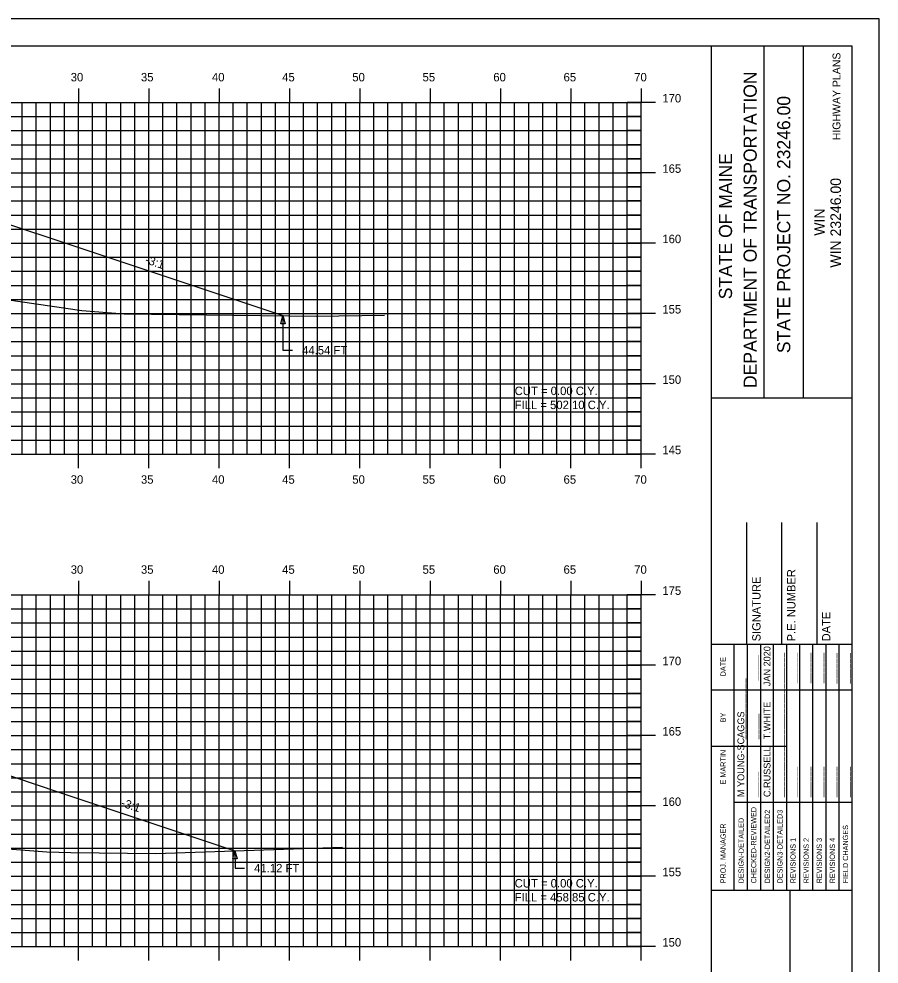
# Model space of a CAD drawing. Extents: x 1140981 to 1141151, y 608981 to 609091.
# Drawn here: x 1141089.5 to 1141150.7, y 609024.1 to 609091.3 of the extents above; entities that cross this region are included whole.
import ezdxf

# ---------------------------------------------------------------- set-up
doc = ezdxf.new("R2010")
doc.units = 0
for name, color, linetype in [('ANNOTATION', 7, 'Continuous'), ('BORDER', 7, 'Continuous'), ('D_Roadway_SlopeLines', 7, 'Continuous'), ('D_Text_Standard', 7, 'Continuous'), ('H_V ANNOTATION', 7, 'Continuous'), ('HIGHWAY_TITLE', 7, 'Continuous'), ('MAJOR', 7, 'Continuous'), ('MINOR', 7, 'Continuous'), ('PLOT BOUNDARY', 7, 'Continuous'), ('S_Roadway_Centerline', 7, 'Continuous')]:
    doc.layers.add(name, color=color, linetype=linetype)

msp = doc.modelspace()

# ---------------------------------------------------------------- linework, layer by layer
for points in [[(1141018.694, 609070.301), (1141034.295, 609075.501), (1141037.295, 609076.501), (1141044.764, 609078.991), (1141044.765, 609078.991), (1141052.758, 609079.311), (1141063.758, 609079.531), (1141074.758, 609079.311), (1141081.758, 609079.031), (1141089.29, 609076.52), (1141092.29, 609075.52), (1141108.295, 609070.185)], [(1141015.324, 609031.014), (1141031.055, 609036.258), (1141034.055, 609037.258), (1141041.302, 609039.673), (1141041.303, 609039.673), (1141052.758, 609040.132), (1141063.758, 609040.352), (1141074.758, 609040.132), (1141081.758, 609039.852), (1141089.29, 609037.341), (1141092.29, 609036.341), (1141104.882, 609032.144)]]:
    msp.add_lwpolyline(points)
at = {"layer": 'BORDER'}
for p, q in [((1141138.758, 608984.335), (1141138.758, 609089.335)), ((1141142.486, 609064.332), (1141142.486, 609089.332)), ((1141145.281, 609064.332), (1141145.281, 609089.332)), ((1141138.759, 609064.329), (1141148.758, 609064.329)), ((1141141.258, 609046.838), (1141141.258, 609055.485)), ((1141143.758, 609046.838), (1141143.758, 609055.485)), ((1141146.258, 609046.838), (1141146.258, 609055.485)), ((1141138.758, 609046.838), (1141148.758, 609046.838)), ((1141138.758, 609029.338), (1141148.758, 609029.338)), ((1141144.349, 608994.338), (1141144.349, 609029.338))]:
    msp.add_line(p, q, dxfattribs=at)
msp.add_lwpolyline([(1140988.758, 608984.335), (1141148.758, 608984.335), (1141148.758, 609089.335), (1140988.758, 609089.335)], close=True, dxfattribs=at)
for points in [[(1141140.373, 609043.588), (1141140.373, 609046.838)], [(1141141.305, 609029.341), (1141141.305, 609046.838)], [(1141142.237, 609046.838), (1141142.237, 609029.341)], [(1141143.169, 609029.341), (1141143.169, 609046.838)], [(1141144.1, 609029.341), (1141144.1, 609046.838)], [(1141145.032, 609029.341), (1141145.032, 609046.838)], [(1141145.964, 609029.341), (1141145.964, 609046.838)], [(1141146.895, 609029.341), (1141146.895, 609046.838)], [(1141147.827, 609029.341), (1141147.827, 609046.838)], [(1141140.374, 609029.341), (1141140.374, 609046.132)], [(1141138.758, 609043.588), (1141148.758, 609043.588)], [(1141138.758, 609039.588), (1141140.374, 609039.588)], [(1141140.373, 609039.588), (1141144.099, 609039.588)], [(1141140.373, 609035.588), (1141148.758, 609035.588)]]:
    msp.add_lwpolyline(points, dxfattribs=at)
at = {"layer": 'D_Roadway_SlopeLines'}
for points in [[(1141089.29, 609076.52), (1141092.29, 609075.52)], [(1141092.29, 609075.52), (1141108.295, 609070.185)], [(1141089.29, 609037.341), (1141092.29, 609036.341)], [(1141092.29, 609036.341), (1141104.882, 609032.144)]]:
    msp.add_lwpolyline(points, dxfattribs=at)
at = {"layer": 'D_Text_Standard'}
for points in [[(1141108.295, 609070.185), (1141108.44, 609069.603), (1141108.149, 609069.603)], [(1141104.882, 609032.144), (1141105.028, 609031.562), (1141104.737, 609031.561)]]:
    msp.add_lwpolyline(points, close=True, dxfattribs=at)
for points in [[(1141108.295, 609070.185), (1141108.292, 609067.726), (1141108.972, 609067.726)], [(1141104.882, 609032.144), (1141104.884, 609030.908), (1141105.564, 609030.908)]]:
    msp.add_lwpolyline(points, dxfattribs=at)
at = {"layer": 'MAJOR'}
for p, q in [((1141093.758, 609086.337), (1141093.758, 609085.335)), ((1141098.758, 609086.337), (1141098.758, 609085.335)), ((1141103.758, 609086.337), (1141103.758, 609085.335)), ((1141108.758, 609086.337), (1141108.758, 609085.335)), ((1141113.758, 609086.337), (1141113.758, 609085.335)), ((1141118.758, 609086.337), (1141118.758, 609085.335)), ((1141123.758, 609086.337), (1141123.758, 609085.335)), ((1141128.758, 609086.337), (1141128.758, 609085.335)), ((1141133.758, 609086.337), (1141133.758, 609085.335)), ((1140993.758, 609085.335), (1141133.758, 609085.335)), ((1140993.758, 609085.335), (1141133.758, 609085.335)), ((1141093.758, 609060.335), (1141093.758, 609085.335)), ((1141098.758, 609060.335), (1141098.758, 609085.335)), ((1141103.758, 609060.335), (1141103.758, 609085.335)), ((1141108.758, 609060.335), (1141108.758, 609085.335)), ((1141113.758, 609060.335), (1141113.758, 609085.335)), ((1141118.758, 609060.335), (1141118.758, 609085.335)), ((1141123.758, 609060.335), (1141123.758, 609085.335)), ((1141128.758, 609060.335), (1141128.758, 609085.335)), ((1141134.76, 609085.335), (1141132.756, 609085.335)), ((1141133.758, 609060.335), (1141133.758, 609085.335)), ((1141133.758, 609060.335), (1141133.758, 609085.335)), ((1140993.758, 609080.335), (1141133.758, 609080.335)), ((1141134.76, 609080.335), (1141132.756, 609080.335)), ((1140993.758, 609075.335), (1141133.758, 609075.335)), ((1141134.76, 609075.335), (1141132.756, 609075.335)), ((1140993.758, 609070.335), (1141133.758, 609070.335)), ((1141134.76, 609070.335), (1141132.756, 609070.335)), ((1140993.758, 609065.335), (1141133.758, 609065.335)), ((1141134.76, 609065.335), (1141132.756, 609065.335)), ((1140993.758, 609060.335), (1141133.758, 609060.335)), ((1140993.758, 609060.335), (1141133.758, 609060.335)), ((1141093.758, 609059.333), (1141093.758, 609060.335)), ((1141098.758, 609059.333), (1141098.758, 609060.335)), ((1141103.758, 609059.333), (1141103.758, 609060.335)), ((1141108.758, 609059.333), (1141108.758, 609060.335)), ((1141113.758, 609059.333), (1141113.758, 609060.335)), ((1141118.758, 609059.333), (1141118.758, 609060.335)), ((1141123.758, 609059.333), (1141123.758, 609060.335)), ((1141128.758, 609059.333), (1141128.758, 609060.335)), ((1141134.76, 609060.335), (1141132.756, 609060.335)), ((1141133.758, 609059.333), (1141133.758, 609060.335)), ((1141093.758, 609051.337), (1141093.758, 609050.335)), ((1141098.758, 609051.337), (1141098.758, 609050.335)), ((1141103.758, 609051.337), (1141103.758, 609050.335)), ((1141108.758, 609051.337), (1141108.758, 609050.335)), ((1141113.758, 609051.337), (1141113.758, 609050.335)), ((1141118.758, 609051.337), (1141118.758, 609050.335)), ((1141123.758, 609051.337), (1141123.758, 609050.335)), ((1141128.758, 609051.337), (1141128.758, 609050.335)), ((1141133.758, 609051.337), (1141133.758, 609050.335)), ((1140993.758, 609050.335), (1141133.758, 609050.335)), ((1140993.758, 609050.335), (1141133.758, 609050.335)), ((1141093.758, 609025.335), (1141093.758, 609050.335)), ((1141098.758, 609025.335), (1141098.758, 609050.335)), ((1141103.758, 609025.335), (1141103.758, 609050.335)), ((1141108.758, 609025.335), (1141108.758, 609050.335)), ((1141113.758, 609025.335), (1141113.758, 609050.335)), ((1141118.758, 609025.335), (1141118.758, 609050.335)), ((1141123.758, 609025.335), (1141123.758, 609050.335)), ((1141128.758, 609025.335), (1141128.758, 609050.335)), ((1141134.76, 609050.335), (1141132.756, 609050.335)), ((1141133.758, 609025.335), (1141133.758, 609050.335)), ((1141133.758, 609025.335), (1141133.758, 609050.335)), ((1140993.758, 609045.335), (1141133.758, 609045.335)), ((1141134.76, 609045.335), (1141132.756, 609045.335)), ((1140993.758, 609040.335), (1141133.758, 609040.335)), ((1141134.76, 609040.335), (1141132.756, 609040.335)), ((1140993.758, 609035.335), (1141133.758, 609035.335)), ((1141134.76, 609035.335), (1141132.756, 609035.335)), ((1140993.758, 609030.335), (1141133.758, 609030.335)), ((1141134.76, 609030.335), (1141132.756, 609030.335)), ((1140993.758, 609025.335), (1141133.758, 609025.335)), ((1140993.758, 609025.335), (1141133.758, 609025.335)), ((1141093.758, 609024.333), (1141093.758, 609025.335)), ((1141098.758, 609024.333), (1141098.758, 609025.335)), ((1141103.758, 609024.333), (1141103.758, 609025.335)), ((1141108.758, 609024.333), (1141108.758, 609025.335)), ((1141113.758, 609024.333), (1141113.758, 609025.335)), ((1141118.758, 609024.333), (1141118.758, 609025.335)), ((1141123.758, 609024.333), (1141123.758, 609025.335)), ((1141128.758, 609024.333), (1141128.758, 609025.335)), ((1141134.76, 609025.335), (1141132.756, 609025.335)), ((1141133.758, 609024.333), (1141133.758, 609025.335))]:
    msp.add_line(p, q, dxfattribs=at)
at = {"layer": 'MINOR'}
for p, q in [((1141089.758, 609060.335), (1141089.758, 609085.335)), ((1141090.758, 609060.335), (1141090.758, 609085.335)), ((1141091.758, 609060.335), (1141091.758, 609085.335)), ((1141092.758, 609060.335), (1141092.758, 609085.335)), ((1141094.758, 609060.335), (1141094.758, 609085.335)), ((1141095.758, 609060.335), (1141095.758, 609085.335)), ((1141096.758, 609060.335), (1141096.758, 609085.335)), ((1141097.758, 609060.335), (1141097.758, 609085.335)), ((1141099.758, 609060.335), (1141099.758, 609085.335)), ((1141100.758, 609060.335), (1141100.758, 609085.335)), ((1141101.758, 609060.335), (1141101.758, 609085.335)), ((1141102.758, 609060.335), (1141102.758, 609085.335)), ((1141104.758, 609060.335), (1141104.758, 609085.335)), ((1141105.758, 609060.335), (1141105.758, 609085.335)), ((1141106.758, 609060.335), (1141106.758, 609085.335)), ((1141107.758, 609060.335), (1141107.758, 609085.335)), ((1141109.758, 609060.335), (1141109.758, 609085.335)), ((1141110.758, 609060.335), (1141110.758, 609085.335)), ((1141111.758, 609060.335), (1141111.758, 609085.335)), ((1141112.758, 609060.335), (1141112.758, 609085.335)), ((1141114.758, 609060.335), (1141114.758, 609085.335)), ((1141115.758, 609060.335), (1141115.758, 609085.335)), ((1141116.758, 609060.335), (1141116.758, 609085.335)), ((1141117.758, 609060.335), (1141117.758, 609085.335)), ((1141119.758, 609060.335), (1141119.758, 609085.335)), ((1141120.758, 609060.335), (1141120.758, 609085.335)), ((1141121.758, 609060.335), (1141121.758, 609085.335)), ((1141122.758, 609060.335), (1141122.758, 609085.335)), ((1141124.758, 609060.335), (1141124.758, 609085.335)), ((1141125.758, 609060.335), (1141125.758, 609085.335)), ((1141126.758, 609060.335), (1141126.758, 609085.335)), ((1141127.758, 609060.335), (1141127.758, 609085.335)), ((1141129.758, 609060.335), (1141129.758, 609085.335)), ((1141130.758, 609060.335), (1141130.758, 609085.335)), ((1141131.758, 609060.335), (1141131.758, 609085.335)), ((1141132.758, 609060.335), (1141132.758, 609085.335)), ((1140993.758, 609084.335), (1141133.758, 609084.335)), ((1141133.758, 609084.335), (1141132.756, 609084.335)), ((1140993.758, 609083.335), (1141133.758, 609083.335)), ((1141133.758, 609083.335), (1141132.756, 609083.335)), ((1140993.758, 609082.335), (1141133.758, 609082.335)), ((1141133.758, 609082.335), (1141132.756, 609082.335)), ((1140993.758, 609081.335), (1141133.758, 609081.335)), ((1141133.758, 609081.335), (1141132.756, 609081.335)), ((1140993.758, 609079.335), (1141133.758, 609079.335)), ((1141133.758, 609079.335), (1141132.756, 609079.335)), ((1140993.758, 609078.335), (1141133.758, 609078.335)), ((1141133.758, 609078.335), (1141132.756, 609078.335)), ((1140993.758, 609077.335), (1141133.758, 609077.335)), ((1141133.758, 609077.335), (1141132.756, 609077.335)), ((1140993.758, 609076.335), (1141133.758, 609076.335)), ((1141133.758, 609076.335), (1141132.756, 609076.335)), ((1140993.758, 609074.335), (1141133.758, 609074.335)), ((1141133.758, 609074.335), (1141132.756, 609074.335)), ((1140993.758, 609073.335), (1141133.758, 609073.335)), ((1141133.758, 609073.335), (1141132.756, 609073.335)), ((1140993.758, 609072.335), (1141133.758, 609072.335)), ((1141133.758, 609072.335), (1141132.756, 609072.335)), ((1140993.758, 609071.335), (1141133.758, 609071.335)), ((1141133.758, 609071.335), (1141132.756, 609071.335)), ((1140993.758, 609069.335), (1141133.758, 609069.335)), ((1141133.758, 609069.335), (1141132.756, 609069.335)), ((1140993.758, 609068.335), (1141133.758, 609068.335)), ((1141133.758, 609068.335), (1141132.756, 609068.335)), ((1140993.758, 609067.335), (1141133.758, 609067.335)), ((1141133.758, 609067.335), (1141132.756, 609067.335)), ((1140993.758, 609066.335), (1141133.758, 609066.335)), ((1141133.758, 609066.335), (1141132.756, 609066.335)), ((1140993.758, 609064.335), (1141133.758, 609064.335)), ((1141133.758, 609064.335), (1141132.756, 609064.335)), ((1140993.758, 609063.335), (1141133.758, 609063.335)), ((1141133.758, 609063.335), (1141132.756, 609063.335)), ((1140993.758, 609062.335), (1141133.758, 609062.335)), ((1141133.758, 609062.335), (1141132.756, 609062.335)), ((1140993.758, 609061.335), (1141133.758, 609061.335)), ((1141133.758, 609061.335), (1141132.756, 609061.335)), ((1141089.758, 609025.335), (1141089.758, 609050.335)), ((1141090.758, 609025.335), (1141090.758, 609050.335)), ((1141091.758, 609025.335), (1141091.758, 609050.335)), ((1141092.758, 609025.335), (1141092.758, 609050.335)), ((1141094.758, 609025.335), (1141094.758, 609050.335)), ((1141095.758, 609025.335), (1141095.758, 609050.335)), ((1141096.758, 609025.335), (1141096.758, 609050.335)), ((1141097.758, 609025.335), (1141097.758, 609050.335)), ((1141099.758, 609025.335), (1141099.758, 609050.335)), ((1141100.758, 609025.335), (1141100.758, 609050.335)), ((1141101.758, 609025.335), (1141101.758, 609050.335)), ((1141102.758, 609025.335), (1141102.758, 609050.335)), ((1141104.758, 609025.335), (1141104.758, 609050.335)), ((1141105.758, 609025.335), (1141105.758, 609050.335)), ((1141106.758, 609025.335), (1141106.758, 609050.335)), ((1141107.758, 609025.335), (1141107.758, 609050.335)), ((1141109.758, 609025.335), (1141109.758, 609050.335)), ((1141110.758, 609025.335), (1141110.758, 609050.335)), ((1141111.758, 609025.335), (1141111.758, 609050.335)), ((1141112.758, 609025.335), (1141112.758, 609050.335)), ((1141114.758, 609025.335), (1141114.758, 609050.335)), ((1141115.758, 609025.335), (1141115.758, 609050.335)), ((1141116.758, 609025.335), (1141116.758, 609050.335)), ((1141117.758, 609025.335), (1141117.758, 609050.335)), ((1141119.758, 609025.335), (1141119.758, 609050.335)), ((1141120.758, 609025.335), (1141120.758, 609050.335)), ((1141121.758, 609025.335), (1141121.758, 609050.335)), ((1141122.758, 609025.335), (1141122.758, 609050.335)), ((1141124.758, 609025.335), (1141124.758, 609050.335)), ((1141125.758, 609025.335), (1141125.758, 609050.335)), ((1141126.758, 609025.335), (1141126.758, 609050.335)), ((1141127.758, 609025.335), (1141127.758, 609050.335)), ((1141129.758, 609025.335), (1141129.758, 609050.335)), ((1141130.758, 609025.335), (1141130.758, 609050.335)), ((1141131.758, 609025.335), (1141131.758, 609050.335)), ((1141132.758, 609025.335), (1141132.758, 609050.335)), ((1140993.758, 609049.335), (1141133.758, 609049.335)), ((1141133.758, 609049.335), (1141132.756, 609049.335)), ((1140993.758, 609048.335), (1141133.758, 609048.335)), ((1141133.758, 609048.335), (1141132.756, 609048.335)), ((1140993.758, 609047.335), (1141133.758, 609047.335)), ((1141133.758, 609047.335), (1141132.756, 609047.335)), ((1140993.758, 609046.335), (1141133.758, 609046.335)), ((1141133.758, 609046.335), (1141132.756, 609046.335)), ((1140993.758, 609044.335), (1141133.758, 609044.335)), ((1141133.758, 609044.335), (1141132.756, 609044.335)), ((1140993.758, 609043.335), (1141133.758, 609043.335)), ((1141133.758, 609043.335), (1141132.756, 609043.335)), ((1140993.758, 609042.335), (1141133.758, 609042.335)), ((1141133.758, 609042.335), (1141132.756, 609042.335)), ((1140993.758, 609041.335), (1141133.758, 609041.335)), ((1141133.758, 609041.335), (1141132.756, 609041.335)), ((1140993.758, 609039.335), (1141133.758, 609039.335)), ((1141133.758, 609039.335), (1141132.756, 609039.335)), ((1140993.758, 609038.335), (1141133.758, 609038.335)), ((1141133.758, 609038.335), (1141132.756, 609038.335)), ((1140993.758, 609037.335), (1141133.758, 609037.335)), ((1141133.758, 609037.335), (1141132.756, 609037.335)), ((1140993.758, 609036.335), (1141133.758, 609036.335)), ((1141133.758, 609036.335), (1141132.756, 609036.335)), ((1140993.758, 609034.335), (1141133.758, 609034.335)), ((1141133.758, 609034.335), (1141132.756, 609034.335)), ((1140993.758, 609033.335), (1141133.758, 609033.335)), ((1141133.758, 609033.335), (1141132.756, 609033.335)), ((1140993.758, 609032.335), (1141133.758, 609032.335)), ((1141133.758, 609032.335), (1141132.756, 609032.335)), ((1140993.758, 609031.335), (1141133.758, 609031.335)), ((1141133.758, 609031.335), (1141132.756, 609031.335)), ((1140993.758, 609029.335), (1141133.758, 609029.335)), ((1141133.758, 609029.335), (1141132.756, 609029.335)), ((1140993.758, 609028.335), (1141133.758, 609028.335)), ((1141133.758, 609028.335), (1141132.756, 609028.335)), ((1140993.758, 609027.335), (1141133.758, 609027.335)), ((1141133.758, 609027.335), (1141132.756, 609027.335)), ((1140993.758, 609026.335), (1141133.758, 609026.335)), ((1141133.758, 609026.335), (1141132.756, 609026.335))]:
    msp.add_line(p, q, dxfattribs=at)
at = {"layer": 'PLOT BOUNDARY'}
msp.add_lwpolyline([(1140980.664, 608981.276), (1141150.664, 608981.276), (1141150.664, 609091.276), (1140980.664, 609091.276)], close=True, dxfattribs=at)
at = {"layer": 'S_Roadway_Centerline'}
for points in [[(1140993.758, 609070.235), (1141016.927, 609070.323), (1141025.835, 609070.211), (1141031.23, 609070.816), (1141045.025, 609071.913), (1141046.887, 609072.758), (1141050.236, 609074.313), (1141052.144, 609074.689), (1141053.6, 609074.965), (1141057.959, 609075.178), (1141064.255, 609075.378), (1141069.594, 609075.216), (1141075.604, 609075.039), (1141077.446, 609074.821), (1141079.228, 609074.497), (1141085.647, 609072.383), (1141088.632, 609071.329), (1141093.986, 609070.537), (1141096.999, 609070.318), (1141110.65, 609070.157), (1141115.506, 609070.212)], [(1140993.758, 609030.733), (1141009.977, 609030.874), (1141026.763, 609031.313), (1141030.432, 609031.56), (1141045.208, 609032.752), (1141047.834, 609033.947), (1141049.661, 609034.555), (1141051.778, 609034.94), (1141052.932, 609035.025), (1141057.344, 609035.19), (1141063.779, 609035.507), (1141070.513, 609035.304), (1141074.764, 609035.173), (1141076.322, 609035.016), (1141078.692, 609034.736), (1141083.759, 609032.911), (1141084.999, 609032.561), (1141091.498, 609032.059), (1141093.213, 609032.024), (1141099.245, 609031.951), (1141112.53, 609032.405)]]:
    msp.add_lwpolyline(points, dxfattribs=at)

# ---------------------------------------------------------------- texts
at = {"layer": 'ANNOTATION'}
for p in [(1141098.442, 609073.923), (1141096.735, 609035.313)]:
    msp.add_text('-3:1', height=0.6, rotation=341.56505, dxfattribs=at).set_placement(p)
at = {"layer": 'BORDER'}
for s, height, p in [('DEPARTMENT OF TRANSPORTATION', 0.93176, (1141141.965, 609065.041)), ('STATE PROJECT NO. 23246.00', 0.93176, (1141144.35, 609067.517)), ('STATE OF MAINE', 0.93176, (1141140.213, 609071.347)), ('WIN 23246.00', 0.74527, (1141147.953, 609073.596)), ('WIN', 0.7453, (1141146.795, 609075.865)), ('P.E. NUMBER', 0.59055, (1141144.719, 609047.03)), ('SIGNATURE', 0.5906, (1141142.238, 609047.03)), ('DATE', 0.5906, (1141147.199, 609047.03)), ('JAN 2020', 0.4845, (1141142.944, 609043.843)), ('DATE', 0.3714, (1141139.762, 609044.544)), ('_____', 0.4845, (1141141.975, 609044.243)), ('______', 0.4845, (1141143.839, 609044.063)), ('______', 0.4845, (1141144.77, 609044.065)), ('______', 0.4845, (1141145.702, 609044.067)), ('______', 0.4845, (1141146.634, 609044.067)), ('______', 0.4845, (1141147.565, 609044.036)), ('______', 0.4845, (1141148.497, 609044.036)), ('____________', 0.48455, (1141141.081, 609040.073)), ('____________', 0.48455, (1141143.839, 609040.073)), ('T.WHITE', 0.4845, (1141142.944, 609040.073)), ('BY', 0.3714, (1141139.762, 609041.273)), ('M YOUNG-SCAGGS', 0.48455, (1141141.081, 609035.961)), ('_____', 0.4845, (1141142.012, 609040.073)), ('____________', 0.48455, (1141143.839, 609035.961)), ('E MARTIN', 0.3727, (1141139.762, 609036.855)), ('C.RUSSELL', 0.4845, (1141142.944, 609035.961)), ('_____', 0.4845, (1141141.975, 609035.961)), ('______', 0.4845, (1141144.77, 609035.961)), ('______', 0.4845, (1141145.702, 609035.961)), ('______', 0.4845, (1141146.634, 609035.961)), ('______', 0.4845, (1141147.565, 609035.961)), ('______', 0.4845, (1141148.497, 609035.961)), ('CHECKED-REVIEWED', 0.37275, (1141141.939, 609029.826)), ('DESIGN2-DETAILED2', 0.37275, (1141142.908, 609029.826)), ('DESIGN3-DETAILED3', 0.37275, (1141143.802, 609029.826)), ('DESIGN-DETAILED', 0.37275, (1141141.044, 609029.826)), ('PROJ. MANAGER', 0.37275, (1141139.762, 609029.826)), ('FIELD CHANGES', 0.37275, (1141148.461, 609029.826)), ('REVISIONS 1', 0.37275, (1141144.734, 609029.826)), ('REVISIONS 2', 0.37275, (1141145.666, 609029.826)), ('REVISIONS 3', 0.37275, (1141146.597, 609029.826)), ('REVISIONS 4', 0.37275, (1141147.529, 609029.826))]:
    msp.add_text(s, height=height, rotation=90, dxfattribs=at).set_placement(p)
at = {"layer": 'D_Text_Standard'}
for s, p in [('44.54 FT', (1141109.652, 609067.426)), ('CUT = 0.00 C.Y.', (1141124.758, 609064.535)), ('FILL = 502.10 C.Y.', (1141124.758, 609063.539)), ('41.12 FT', (1141106.244, 609030.608)), ('CUT = 0.00 C.Y.', (1141124.758, 609029.535)), ('FILL = 458.85 C.Y.', (1141124.758, 609028.539))]:
    msp.add_text(s, height=0.6, dxfattribs=at).set_placement(p)
at = {"layer": 'H_V ANNOTATION'}
for s, p in [('30', (1141093.206, 609086.835)), ('35', (1141098.198, 609086.835)), ('40', (1141103.244, 609086.835)), ('45', (1141108.236, 609086.835)), ('50', (1141113.222, 609086.835)), ('55', (1141118.214, 609086.835)), ('60', (1141123.244, 609086.835)), ('65', (1141128.236, 609086.835)), ('70', (1141133.26, 609086.835)), ('170', (1141135.258, 609085.335)), ('165', (1141135.258, 609080.335)), ('160', (1141135.258, 609075.335)), ('155', (1141135.258, 609070.335)), ('150', (1141135.258, 609065.335)), ('145', (1141135.258, 609060.335)), ('30', (1141093.206, 609058.235)), ('35', (1141098.198, 609058.235)), ('40', (1141103.244, 609058.235)), ('45', (1141108.236, 609058.235)), ('50', (1141113.222, 609058.235)), ('55', (1141118.214, 609058.235)), ('60', (1141123.244, 609058.235)), ('65', (1141128.236, 609058.235)), ('70', (1141133.26, 609058.235)), ('30', (1141093.206, 609051.835)), ('35', (1141098.198, 609051.835)), ('40', (1141103.244, 609051.835)), ('45', (1141108.236, 609051.835)), ('50', (1141113.222, 609051.835)), ('55', (1141118.214, 609051.835)), ('60', (1141123.244, 609051.835)), ('65', (1141128.236, 609051.835)), ('70', (1141133.26, 609051.835)), ('175', (1141135.258, 609050.335)), ('170', (1141135.258, 609045.335)), ('165', (1141135.258, 609040.335)), ('160', (1141135.258, 609035.335)), ('155', (1141135.258, 609030.335)), ('150', (1141135.258, 609025.335))]:
    msp.add_text(s, height=0.6, dxfattribs=at).set_placement(p)
at = {"layer": 'HIGHWAY_TITLE'}
msp.add_text('HIGHWAY PLANS', height=0.55901, rotation=90, dxfattribs=at).set_placement((1141147.916, 609082.65))

doc.saveas('drawing.dxf')
